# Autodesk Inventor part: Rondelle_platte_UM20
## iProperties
Library Location: C:\Program Files\Autodesk\Inventor 6\content
Library: local
SubLibrary: ISO
Family: 62
Member: 140
Member Major Revision: 1
Member Minor Revision: 1
Comments: To add or edit properties for Autodesk Inventor files, use iProperties.
Created: 2008-02
Part Number: Rondelle_platte_UM20
Vendor: Autodesk Inc.
Document SubType Name: Modeling
Designer: Pascal
Description: Rondelle
Standard: ISO 7089 20 - 140 HV
Alert: To add or edit properties for Autodesk Inventor files, use iProperties.
Control State: 0
Master: False
Checked Out: False
Shininess: 64.0
Length Units: 11269
Angle Units: 11279
Time Units: 11290
Mass Units: 11283
Length Display Precision: 3
Angle Display Precision: 2
Compacted: True
Classification: un/spsc 31161807
Density: 0.0
Volumn: 0.0
Area: 0.0
PropertySet Name: Model Information
Author: Pascal
Revision Number: 1
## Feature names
1. Body [Extrusion]
